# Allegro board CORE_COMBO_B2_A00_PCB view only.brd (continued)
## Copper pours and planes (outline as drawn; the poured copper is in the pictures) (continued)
N41930622 on TOP (solid shape): 121.73,125.34 121.73,123.99 121.98,123.74 121.98,122.04 121.85,121.91 121.22,121.91 121.09,122.04 121.09,124.45 120.84,124.7 120.84,125.34 120.97,125.46 121.6,125.46
N41930626 on TOP (solid shape): 123.51,124.4 123.51,123.56 123.3,123.36 123.3,122.01 123.25,121.96 122.79,121.96 122.74,122.01 122.74,123.43 123,123.69 123.15,123.69 123.25,123.79 123.25,124.4 123.28,124.42 123.48,124.42
N41930661 on BOTTOM (solid shape): 125.09,125.78 125.09,123.88 125.03,123.81 124.01,123.81 123.95,123.88 123.95,124.79 124.07,125.08 123.95,125.38 123.95,125.78 124.08,125.91 124.97,125.91
N41935085 on TOP (solid shape): 63.69,99.94 63.69,98.42 63.56,98.29 62.55,98.29 62.42,98.42 62.42,100.19 62.55,100.32 63.31,100.32
N41935204 on TOP (solid shape): 59.86,92.57 59.86,92.45 59.83,92.42 59.5,92.42 58.9,92.1 58.63,92.08 58.44,91.89 58.43,91.89 58.33,91.78 57.39,91.78 57.36,91.81 57.36,92.46 57.51,92.6 59.83,92.6
N41935208 on TOP (solid shape): 56.61,93.92 56.61,92.59 56.61,92.53 56.61,91.92 56.58,91.88 56.04,91.88 55.98,91.95 55.98,93.94 56.02,93.98 56.55,93.98
N41935210 on TOP (solid shape): 59.5,92.98 59.83,92.98 59.86,92.95 59.86,92.85 59.83,92.83 58.97,92.83 58.95,92.84 58.59,92.98 57.44,92.98 57.43,92.96 57.36,93.03 57.36,93.79 57.41,93.84 58.19,93.84
N42702326 on BOTTOM (solid shape): 176.44,100.47 176.44,98.26 176.36,98.18 175.91,98.18 175.81,98.28 175.81,99.82 175.68,99.94 175.68,100.92 175.72,100.95 175.96,100.95
N42704390 on TOP (solid shape): 216.47,59.04 216.47,58.28 216.41,58.22 215.8,58.22 215.56,58.46 214.98,58.46 214.98,59.32 216.19,59.32
N42704539 on TOP (solid shape): 191.4,111.06 191.4,109.72 191.37,109.69 190.49,109.69 190.38,109.79 190.38,111.06 190.54,111.21 191.25,111.21
N42707454 on TOP (solid shape): 216.42,51.17 216.42,50.41 216.29,50.28 215.02,50.28 214.89,50.41 214.89,51.17 215.02,51.3 216.29,51.3
N42743777 on TOP (solid shape): 91.5,114.19 91.5,110.73 91.37,110.61 90.1,110.61 89.98,110.73 89.98,113.02 90.74,113.78 90.74,114.19 90.79,114.24 91.45,114.24
N42775282 on TOP (solid shape): 192.59,68.19 192.59,64.66 194.04,63.21 194.8,63.21 194.83,63.18 194.83,63.03 194.8,63.01 193.84,63.01 192.48,63.73 192.09,64.12 191.7,64.12 191.45,64.38 191.45,68.19 191.7,68.44 192.34,68.44
N42775282 on BOTTOM (solid shape): 196.51,65.16 196.65,64.84 196.97,64.7 197.31,64.36 197.6,63.96 198.09,64 199.32,64 199.83,63.49 199.83,62.85 199.71,62.73 197.04,62.73 195.06,64.71 194.58,64.71 194.53,64.75 194.32,64.88 194.08,64.85 192.25,64.85 191.96,65.14 191.96,65.65 192.09,65.77 195.9,65.77
N43141708 on BOTTOM (solid shape): outline of 133 points within 164.76,121.45 176.08,125.67
N43141816 on BOTTOM (solid shape): 176.97,134.62 176.97,134.28 176.81,134.11 167.05,134.11 166.58,133.64 166.58,130.42 163.13,130.42 163.07,130.48 163.07,132.58 163.89,132.58 166.04,134.72 176.87,134.72
N46095567 on TOP (solid shape): 69.2,138.85 68.36,138.85 68.36,140.48 69.2,140.48
N46939475 on TOP (solid shape): 190.86,22.43 191.77,22.43 191.81,22.39 191.81,21.98 191.76,21.93 189.58,21.93 189.54,21.97 189.54,22.47 189.6,22.53 190.76,22.53
N46939475 on BOTTOM (solid shape): 191.79,22.69 191.79,22.02 191.79,22.02 191.7,21.93 189.77,21.93 189.62,22.08 189.62,22.35 190.13,22.86 191.61,22.86
N46939509 on TOP (solid shape): 186.51,23.8 186.51,21.93 186.5,21.92 182.92,21.92 182.76,22.08 182.76,23.02 182.84,23.09 183.1,23.09 183.14,23.05 183.14,22.63 183.28,22.5 183.96,22.5 184.06,22.61 184.06,23.02 184.13,23.09 184.39,23.09 184.44,23.04 184.44,22.57 184.5,22.51 184.75,22.51 185.28,23.04 185.28,23.89 185.34,23.95 186.36,23.95
N46939509 on BOTTOM (solid shape): 184.6,23.57 184.52,23.33 184.6,23.09 184.72,22.99 184.88,22.95 185.18,22.65 185.18,22.04 185.06,21.93 183.79,21.93 183.72,22 183.72,23.82 183.89,23.99 184.6,23.99
N46967671 on TOP (solid shape): 195.01,22.81 195.01,22.56 194.38,21.93 193.75,21.93 193.6,22.08 193.6,22.28 193.92,22.6 193.92,22.78 194.05,22.91 194.9,22.91
N46967671 on BOTTOM (solid shape): 192.49,22.83 192.61,22.59 192.86,22.49 194.02,22.49 194.14,22.37 194.14,22.08 193.99,21.93 192.06,21.93 191.94,22.04 191.94,22.78 191.99,22.83
N46967970 on TOP (solid shape): 191.62,25.33 192.08,24.86 192.08,24.57 192.02,24.51 190.99,24.51 190.38,25.12 190.01,25.12 189.93,25.2 189.93,25.55 190.11,25.73 191.22,25.73

Small or netless copper shapes (teardrops, artwork), in the pictures only: 2082 on TOP, 3124 on BOTTOM, 1 on GND1, 671 on IN1, 1 on VCC, 269 on IN2, 566 on IN3, 1 on GND2, 796 on IN4, 1 on GND3

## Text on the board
BOTTOM: list("[Spacing] BOTTOM" "91.Shape to Route Keepin" "0 MIL [DEFAULT]" "0 MIL" "0.00 MIL" "DRC ERROR CLASS/BOTTOM" "[Shape] Route Keepin/All ((-2977.43 -914.53) (7906.82 5074.84))" "[Bottom Shape] GND ((-2977.43 2424.07) (-2857.3 2460.69))" list(-2860.810000 2460.660000) nil)@@@list("kelly1_pan" "2016/03/17 14:49:46" nil "P143000035-PC" "10i-core_combo_b2.20")@@@list("jennifer_hsu" "2016/03/21 14:50:22" nil "p143000039-pc" "10i-core_combo_b2.20") | list("[Spacing] BOTTOM" "96.Shape to Route Keepout" "0 MIL [DEFAULT]" "0 MIL" "0.00 MIL" "DRC ERROR CLASS/BOTTOM" "[Shape] Route Keepout/Bottom ((-2939.39 4419.59) (-2632.39 4726.59))" "[Bottom Shape] GND ((-2977.43 -914.51) (7906.82 5087.85))" list(-2632.390000 4572.890000) nil)@@@list("kelly1_pan" "2016/03/17 14:49:45" nil "P143000035-PC" "10i-core_combo_b2.20")@@@list("jennifer_hsu" "2016/03/21 14:50:30" nil "p143000039-pc" "10i-core_combo_b2.20") | list("[Spacing] BOTTOM" "95.Shape to Route Keepout" "0 MIL [DEFAULT]" "0 MIL" "0.00 MIL" "DRC ERROR CLASS/BOTTOM" "[Shape] Route Keepout/Bottom ((-2348.84 2383.37) (-2041.84 2690.37))" "[Bottom Shape] GND ((-2977.43 -914.51) (7906.82 5087.85))" list(-2091.230000 2424.070000) nil)@@@list("kelly1_pan" "2016/03/17 14:49:44" nil "P143000035-PC" "10i-core_combo_b2.20")@@@list("jennifer_hsu" "2016/03/21 14:50:28" nil "p143000039-pc" "10i-core_combo_b2.20") | list("[Spacing] BOTTOM" "82.Shape to Route Keepin" "0 MIL [DEFAULT]" "0 MIL" "0.00 MIL" "DRC ERROR CLASS/BOTTOM" "[Shape] Route Keepin/All ((-2977.43 -914.53) (7906.82 5074.84))" "[Bottom Shape] GNDA ((-2355.82 4282.82) (-1364.01 4696.91))" list(-1464.240000 4332.710000) nil)@@@list("kelly1_pan" "2016/03/17 14:49:45" nil "P143000035-PC" "10i-core_combo_b2.20")@@@list("jennifer_hsu" "2016/03/21 14:50:10" nil "p143000039-pc" "10i-core_combo_b2.20") | list("[Spacing] BOTTOM" "87.Shape to Route Keepin" "0 MIL [DEFAULT]" "0 MIL" "0.00 MIL" "DRC ERROR CLASS/BOTTOM" "[Shape] Route Keepin/All ((-2977.43 -914.53) (7906.82 5074.84))" "[Bottom Shape] GND ((-1333.98 4144.95) (291.0 5087.85))" list(-1333.980000 4332.710000) nil)@@@list("kelly1_pan" "2016/03/17 14:49:47" nil "P143000035-PC" "10i-core_combo_b2.20")@@@list("jennifer_hsu" "2016/03/21 14:50:16" nil "p143000039-pc" "10i-core_combo_b2.20") | list("[Spacing] BOTTOM" "88.Shape to Route Keepout" "0 MIL [DEFAULT]" "0 MIL" "0.00 MIL" "DRC ERROR CLASS/BOTTOM" "[Shape] Route Keepout/Bottom ((-629.15 4828.23) (-322.15 5135.23))" "[Bottom Shape] GND ((-1333.98 4144.95) (291.0 5087.85))" list(-545.100000 4844.840000) nil)@@@list("kelly1_pan" "2016/03/17 14:49:48" nil "P143000035-PC" "10i-core_combo_b2.20")@@@list("jennifer_hsu" "2016/03/21 14:50:18" nil "p143000039-pc" "10i-core_combo_b2.20") | list("[Spacing] BOTTOM" "97.Drill Hole to Pin" "5 MIL [DEFAULT]" "1.04 MIL" "3.96 MIL" "DRC ERROR CLASS/BOTTOM" "[ThruPin] Dummy (C40D40N) (-294.55 4947.5)" "[ThruPin] GND (<uTiL>cId4188<uTiL>.16) (-270.74 4868.77)" list(-284.640000 4930.130000) nil)@@@list("kelly1_pan" "2016/03/17 14:49:55" nil "P143000035-PC" "10i-core_combo_b2.20")@@@list("jennifer_hsu" "2016/03/21 14:50:32" nil "p143000039-pc" "10i-core_combo_b2.20") | list("[Spacing] BOTTOM" "93.Shape to Route Keepin" "0 MIL [DEFAULT]" "0 MIL" "0.00 MIL" "DRC ERROR CLASS/BOTTOM" "[Shape] Route Keepin/All ((-2977.43 -914.53) (7906.82 5074.84))" "[Bottom Shape] GND ((348.14 4610.0) (1448.58 5074.86))" list(876.750000 4922.470000) nil)@@@list("kelly1_pan" "2016/03/17 14:49:49" nil "P143000035-PC" "10i-core_combo_b2.20")@@@list("jennifer_hsu" "2016/03/21 14:50:25" nil "p143000039-pc" "10i-core_combo_b2.20") | list("[Spacing] BOTTOM" "84.Drill Hole to Pin" "5 MIL [DEFAULT]" "1.05 MIL" "3.95 MIL" "DRC ERROR CLASS/BOTTOM" "[ThruPin] Dummy (C40D40N) (933.78 4947.5)" "[ThruPin] GND (<uTiL>cId4188<uTiL>.17) (909.96 4868.77)" list(923.870000 4930.130000) nil)@@@list("kelly1_pan" "2016/03/17 14:49:39" nil "P143000035-PC" "10i-core_combo_b2.20")@@@list("jennifer_hsu" "2016/03/21 14:50:13" nil "p143000039-pc" "10i-core_combo_b2.20") | list("[Spacing] BOTTOM" "98.Shape to Route Keepin" "0 MIL [DEFAULT]" "0 MIL" "0.00 MIL" "DRC ERROR CLASS/BOTTOM" "[Shape] Route Keepin/All ((-2977.43 -914.53) (7906.82 5074.84))" "[Bottom Shape] GND ((1932.91 4550.54) (2836.64 5074.86))" list(2681.640000 4654.500000) nil)@@@list("kelly1_pan" "2016/03/17 14:49:50" nil "P143000035-PC" "10i-core_combo_b2.20")@@@list("jennifer_hsu" "2016/03/21 14:50:33" nil "p143000039-pc" "10i-core_combo_b2.20") | list("[Spacing] BOTTOM" "83.Shape to Route Keepin" "0 MIL [DEFAULT]" "0 MIL" "0.00 MIL" "DRC ERROR CLASS/BOTTOM" "[Shape] Route Keepin/All ((-2977.43 -914.53) (7906.82 5074.84))" "[Bottom Shape] GND ((3161.34 4517.5) (3444.78 5074.86))" list(3223.730000 4620.110000) nil)@@@list("kelly1_pan" "2016/03/17 14:49:39" nil "P143000035-PC" "10i-core_combo_b2.20")@@@list("jennifer_hsu" "2016/03/21 14:50:12" nil "p143000039-pc" "10i-core_combo_b2.20") | list("[Spacing] BOTTOM" "92.Shape to Route Keepout" "0 MIL [DEFAULT]" "0 MIL" "0.00 MIL" "DRC ERROR CLASS/BOTTOM" "[Shape] Route Keepout/Bottom ((3926.94 3482.78) (4157.17 3713.01))" "[Bottom Shape] GND ((3898.57 3454.37) (4185.57 3741.37))" list(3971.320000 3722.720000) nil)@@@list("kelly1_pan" "2016/03/17 14:49:54" nil "P143000035-PC" "10i-core_combo_b2.20")@@@list("jennifer_hsu" "2016/03/21 14:50:23" nil "p143000039-pc" "10i-core_combo_b2.20") | list("[Spacing] BOTTOM" "99.Shape to Route Keepin" "0 MIL [DEFAULT]" "0 MIL" "0.00 MIL" "DRC ERROR CLASS/BOTTOM" "[Shape] Route Keepin/All ((-2977.43 -914.53) (7906.82 5074.84))" "[Bottom Shape] BATTERY_GND ((5038.71 2723.29) (5493.24 4090.61))" list(5053.080000 2723.290000) nil)@@@list("kelly1_pan" "2016/03/17 14:49:52" nil "P143000035-PC" "10i-core_combo_b2.20")@@@list("jennifer_hsu" "2016/03/21 14:50:34" nil "p143000039-pc" "10i-core_combo_b2.20") | list("[Spacing] BOTTOM" "101.Shape to Route Keepout" "0 MIL [DEFAULT]" "0 MIL" "0.00 MIL" "DRC ERROR CLASS/BOTTOM" "[Shape] Route Keepout/Bottom ((5146.22 3879.01) (5383.2 4115.99))" "[Bottom Shape] BATTERY_GND ((5038.71 2723.29) (5493.24 4090.61))" list(5199.820000 4090.610000) nil)@@@list("kelly1_pan" "2016/03/17 14:49:53" nil "P143000035-PC" "10i-core_combo_b2.20")@@@list("jennifer_hsu" "2016/03/21 14:50:36" nil "p143000039-pc" "10i-core_combo_b2.20") | list("[Spacing] BOTTOM" "100.Shape to Route Keepout" "0 MIL [DEFAULT]" "0 MIL" "0.00 MIL" "DRC ERROR CLASS/BOTTOM" "[Shape] Route Keepout/Bottom ((5146.22 2697.9) (5383.2 2934.88))" "[Bottom Shape] BATTERY_GND ((5038.71 2723.29) (5493.24 4090.61))" list(5343.120000 2898.440000) nil)@@@list("kelly1_pan" "2016/03/17 14:49:53" nil "P143000035-PC" "10i-core_combo_b2.20")@@@list("jennifer_hsu" "2016/03/21 14:50:35" nil "p143000039-pc" "10i-core_combo_b2.20") | list("[Spacing] BOTTOM" "85.Shape to Route Keepin" "0 MIL [DEFAULT]" "0 MIL" "0.00 MIL" "DRC ERROR CLASS/BOTTOM" "[Shape] Route Keepin/All ((-2977.43 -914.53) (7906.82 5074.84))" "[Bottom Shape] AUIDO_GND ((6400.92 2990.01) (7346.97 3893.75))" list(6400.920000 3859.700000) nil)@@@list("kelly1_pan" "2016/03/17 14:49:37" nil "P143000035-PC" "10i-core_combo_b2.20")@@@list("jennifer_hsu" "2016/03/21 14:50:14" nil "p143000039-pc" "10i-core_combo_b2.20") | list("[Spacing] BOTTOM" "90.Shape to Route Keepin" "0 MIL [DEFAULT]" "0 MIL" "0.00 MIL" "DRC ERROR CLASS/BOTTOM" "[Shape] Route Keepin/All ((-2977.43 -914.53) (7906.82 5074.84))" "[Bottom Shape] SIM_GND ((6400.91 2447.7) (7346.98 3320.07))" list(6422.200000 2954.790000) nil)@@@list("kelly1_pan" "2016/03/17 14:49:51" nil "P143000035-PC" "10i-core_combo_b2.20")@@@list("jennifer_hsu" "2016/03/21 14:50:20" nil "p143000039-pc" "10i-core_combo_b2.20") | list("[Spacing] BOTTOM" "86.Shape to Route Keepout" "0 MIL [DEFAULT]" "0 MIL" "0.00 MIL" "DRC ERROR CLASS/BOTTOM" "[Shape] Route Keepout/Bottom ((6465.52 3643.01) (6702.05 3879.55))" "[Bottom Shape] AUIDO_GND ((6400.92 2990.01) (7346.97 3893.75))" list(6702.050000 3759.780000) nil)@@@list("kelly1_pan" "2016/03/17 14:49:38" nil "P143000035-PC" "10i-core_combo_b2.20")@@@list("jennifer_hsu" "2016/03/21 14:50:15" nil "p143000039-pc" "10i-core_combo_b2.20") | list("[Spacing] BOTTOM" "94.Shape to Route Keepin" "0 MIL [DEFAULT]" "0 MIL" "0.00 MIL" "DRC ERROR CLASS/BOTTOM" "[Shape] Route Keepin/All ((-2977.43 -914.53) (7906.82 5074.84))" "[Bottom Shape] GND ((-2977.43 -914.51) (7906.82 5087.85))" list(7110.370000 -900.160000) nil)@@@list("kelly1_pan" "2016/03/17 14:49:40" nil "P143000035-PC" "10i-core_combo_b2.20")@@@list("jennifer_hsu" "2016/03/21 14:50:27" nil "p143000039-pc" "10i-core_combo_b2.20") | list("[Spacing] BOTTOM" "89.Shape to Route Keepout" "0 MIL [DEFAULT]" "0 MIL" "0.00 MIL" "DRC ERROR CLASS/BOTTOM" "[Shape] Route Keepout/Bottom ((7013.55 2440.26) (7250.08 2676.8))" "[Bottom Shape] SIM_GND ((6400.91 2447.7) (7346.98 3320.07))" list(7250.080000 2557.030000) nil)@@@list("kelly1_pan" "2016/03/17 14:49:51" nil "P143000035-PC" "10i-core_combo_b2.20")@@@list("jennifer_hsu" "2016/03/21 14:50:19" nil "p143000039-pc" "10i-core_combo_b2.20")
Ref Des/Silkscreen Bottom: JSIMUAJ1 | JWLAN1 | H16 | JDCIN1 | JSPK1 | JEDP1 | H14 | H13 | JXDP1 | H15 | JRTC1 | JCRT1 | JFAN1 | PJP5813 | JDIMM2 | JDIMM1 | JPSEN1 | JWWAN1 | H18 | JSER1 | JGFX1 | PJP5502 | H19 | JSPI1 | JBAT1 | JDOCK1 | H17 | JUSB2 | JLAN1 | PJP5601 | PJP5603 | JHS1 | PJP5303 | PJP5304 | JIOR1 | JEPC1 | JSEC1 | PJP5812 | JODD1 | PJP5306 | PJP5811 | JRCAM1 | JBAT_PK1 | JBAT_PK2 | JUAJ1 | JSIM1 | JLED1 | JHDMI1 | HDMIU1 | JUSB1 | PJP5913 | PJP5809 | JSTRG1 | PJP5806 | JGPS1 | PJP5602 | PJP5604 | JCSW2 | JSH1 | PJP802 | BOT | 2nd
TOP: list("[Spacing] TOP" "21.Shape to Route Keepin" "0 MIL [DEFAULT]" "0 MIL" "0.00 MIL" "DRC ERROR CLASS/TOP" "[Shape] Route Keepin/All ((-2977.43 -914.53) (7906.82 5074.84))" "[Top Shape] GND ((-2977.43 2424.07) (-2861.29 2460.69))" list(-2864.800000 2460.660000) nil)@@@list("kelly1_pan" "2016/03/17 14:51:45" nil "P143000035-PC" "10i-core_combo_b2.20")@@@list("jennifer_hsu" "2016/03/21 14:48:58" nil "p143000039-pc" "10i-core_combo_b2.20") | list("[Spacing] TOP" "4.Shape to Route Keepin" "0 MIL [DEFAULT]" "0 MIL" "0.00 MIL" "DRC ERROR CLASS/TOP" "[Shape] Route Keepin/All ((-2977.43 -914.53) (7906.82 5074.84))" "[Top Shape] GND ((-2977.43 3702.53) (-2371.51 4709.9))" list(-2660.500000 3717.110000) nil)@@@list("kelly1_pan" "2016/03/17 14:51:54" nil "P143000035-PC" "10i-core_combo_b2.20")@@@list("jennifer_hsu" "2016/03/21 14:48:36" nil "p143000039-pc" "10i-core_combo_b2.20") | list("[Spacing] TOP" "5.Shape to Route Keepout" "0 MIL [DEFAULT]" "0 MIL" "0.00 MIL" "DRC ERROR CLASS/TOP" "[Shape] Route Keepout/Top ((-2939.39 4419.59) (-2632.39 4726.59))" "[Top Shape] GND ((-2977.43 3702.53) (-2371.51 4709.9))" list(-2632.390000 4572.890000) nil)@@@list("kelly1_pan" "2016/03/17 14:51:55" nil "P143000035-PC" "10i-core_combo_b2.20")@@@list("jennifer_hsu" "2016/03/21 14:48:37" nil "p143000039-pc" "10i-core_combo_b2.20") | list("[Spacing] TOP" "20.Shape to Route Keepin" "0 MIL [DEFAULT]" "0 MIL" "0.00 MIL" "DRC ERROR CLASS/TOP" "[Shape] Route Keepin/All ((-2977.43 -914.53) (7906.82 5074.84))" "[Top Shape] GND ((-2977.43 2931.92) (-1940.0 3385.73))" list(-2593.140000 3050.560000) nil)@@@list("kelly1_pan" "2016/03/17 14:51:51" nil "P143000035-PC" "10i-core_combo_b2.20")@@@list("jennifer_hsu" "2016/03/21 14:48:57" nil "p143000039-pc" "10i-core_combo_b2.20") | list("[Spacing] TOP" "11.Shape to Route Keepout" "0 MIL [DEFAULT]" "0 MIL" "0.00 MIL" "DRC ERROR CLASS/TOP" "[Shape] Route Keepout/Top ((-2348.84 2383.37) (-2041.84 2690.37))" "[Top Shape] GND ((-2734.11 -914.51) (7906.82 5087.85))" list(-2091.230000 2424.070000) nil)@@@list("kelly1_pan" "2016/03/17 14:51:48" nil "P143000035-PC" "10i-core_combo_b2.20")@@@list("jennifer_hsu" "2016/03/21 14:48:45" nil "p143000039-pc" "10i-core_combo_b2.20") | list("[Spacing] TOP" "9.Shape to Route Keepin" "0 MIL [DEFAULT]" "0 MIL" "0.00 MIL" "DRC ERROR CLASS/TOP" "[Shape] Route Keepin/All ((-2977.43 -914.53) (7906.82 5074.84))" "[Top Shape] GNDA ((-2355.82 4282.82) (-1364.01 4696.91))" list(-1464.240000 4332.710000) nil)@@@list("kelly1_pan" "2016/03/17 14:51:59" nil "P143000035-PC" "10i-core_combo_b2.20")@@@list("jennifer_hsu" "2016/03/21 14:48:42" nil "p143000039-pc" "10i-core_combo_b2.20") | list("[Spacing] TOP" "14.Shape to Route Keepin" "0 MIL [DEFAULT]" "0 MIL" "0.00 MIL" "DRC ERROR CLASS/TOP" "[Shape] Route Keepin/All ((-2977.43 -914.53) (7906.82 5074.84))" "[Top Shape] GND ((-1333.99 4136.4) (284.0 5087.83))" list(-1333.990000 4332.710000) nil)@@@list("kelly1_pan" "2016/03/17 14:51:58" nil "P143000035-PC" "10i-core_combo_b2.20")@@@list("jennifer_hsu" "2016/03/21 14:48:49" nil "p143000039-pc" "10i-core_combo_b2.20") | list("[Spacing] TOP" "15.Shape to Route Keepout" "0 MIL [DEFAULT]" "0 MIL" "0.00 MIL" "DRC ERROR CLASS/TOP" "[Shape] Route Keepout/Top ((-629.15 4828.23) (-322.15 5135.23))" "[Top Shape] GND ((-1333.99 4136.4) (284.0 5087.83))" list(-545.150000 4844.860000) nil)@@@list("kelly1_pan" "2016/03/17 14:51:58" nil "P143000035-PC" "10i-core_combo_b2.20")@@@list("jennifer_hsu" "2016/03/21 14:48:50" nil "p143000039-pc" "10i-core_combo_b2.20") | list("[Spacing] TOP" "16.Drill Hole to Pin" "5 MIL [DEFAULT]" "1.04 MIL" "3.96 MIL" "DRC ERROR CLASS/TOP" "[ThruPin] Dummy (C40D40N) (-294.55 4947.5)" "[ThruPin] GND (<uTiL>cId4188<uTiL>.16) (-270.74 4868.77)" list(-284.640000 4930.130000) nil)@@@list("kelly1_pan" "2016/03/17 14:52:00" nil "P143000035-PC" "10i-core_combo_b2.20")@@@list("jennifer_hsu" "2016/03/21 14:48:51" nil "p143000039-pc" "10i-core_combo_b2.20") | list("[Spacing] TOP" "13.Shape to Route Keepin" "0 MIL [DEFAULT]" "0 MIL" "0.00 MIL" "DRC ERROR CLASS/TOP" "[Shape] Route Keepin/All ((-2977.43 -914.53) (7906.82 5074.84))" "[Top Shape] GND ((528.0 4712.0) (1448.58 5074.86))" list(687.360000 4922.470000) nil)@@@list("kelly1_pan" "2016/03/17 14:51:46" nil "P143000035-PC" "10i-core_combo_b2.20")@@@list("jennifer_hsu" "2016/03/21 14:48:47" nil "p143000039-pc" "10i-core_combo_b2.20") | list("[Spacing] TOP" "6.Drill Hole to Pin" "5 MIL [DEFAULT]" "1.05 MIL" "3.95 MIL" "DRC ERROR CLASS/TOP" "[ThruPin] Dummy (C40D40N) (933.78 4947.5)" "[ThruPin] GND (<uTiL>cId4188<uTiL>.17) (909.96 4868.77)" list(923.870000 4930.130000) nil)@@@list("kelly1_pan" "2016/03/17 14:51:49" nil "P143000035-PC" "10i-core_combo_b2.20")@@@list("jennifer_hsu" "2016/03/21 14:48:38" nil "p143000039-pc" "10i-core_combo_b2.20") | list("[Spacing] TOP" "12.Shape to Route Keepin" "0 MIL [DEFAULT]" "0 MIL" "0.00 MIL" "DRC ERROR CLASS/TOP" "[Shape] Route Keepin/All ((-2977.43 -914.53) (7906.82 5074.84))" "[Top Shape] GND ((1932.91 4550.54) (2831.6 5074.86))" list(2681.000000 4650.760000) nil)@@@list("kelly1_pan" "2016/03/17 14:51:45" nil "P143000035-PC" "10i-core_combo_b2.20")@@@list("jennifer_hsu" "2016/03/21 14:48:46" nil "p143000039-pc" "10i-core_combo_b2.20") | list("[Spacing] TOP" "3.Shape to Route Keepin" "0 MIL [DEFAULT]" "0 MIL" "0.00 MIL" "DRC ERROR CLASS/TOP" "[Shape] Route Keepin/All ((-2977.43 -914.53) (7906.82 5074.84))" "[Top Shape] GND ((3169.4 4541.5) (3444.78 5074.86))" list(3224.020000 4619.690000) nil)@@@list("kelly1_pan" "2016/03/17 14:51:57" nil "P143000035-PC" "10i-core_combo_b2.20")@@@list("jennifer_hsu" "2016/03/21 14:48:34" nil "p143000039-pc" "10i-core_combo_b2.20") | list("[Spacing] TOP" "19.Shape to Route Keepout" "0 MIL [DEFAULT]" "0 MIL" "0.00 MIL" "DRC ERROR CLASS/TOP" "[Shape] Route Keepout/Top ((5146.22 3879.01) (5383.2 4115.99))" "[Top Shape] BATTERY_GND ((5038.71 2723.29) (5493.24 4090.61))" list(5199.820000 4090.610000) nil)@@@list("kelly1_pan" "2016/03/17 14:51:54" nil "P143000035-PC" "10i-core_combo_b2.20")@@@list("jennifer_hsu" "2016/03/21 14:48:55" nil "p143000039-pc" "10i-core_combo_b2.20") | list("[Spacing] TOP" "18.Shape to Route Keepin" "0 MIL [DEFAULT]" "0 MIL" "0.00 MIL" "DRC ERROR CLASS/TOP" "[Shape] Route Keepin/All ((-2977.43 -914.53) (7906.82 5074.84))" "[Top Shape] BATTERY_GND ((5038.71 2723.29) (5493.24 4090.61))" list(5338.130000 2737.660000) nil)@@@list("kelly1_pan" "2016/03/17 14:51:53" nil "P143000035-PC" "10i-core_combo_b2.20")@@@list("jennifer_hsu" "2016/03/21 14:48:54" nil "p143000039-pc" "10i-core_combo_b2.20") | list("[Spacing] TOP" "17.Shape to Route Keepout" "0 MIL [DEFAULT]" "0 MIL" "0.00 MIL" "DRC ERROR CLASS/TOP" "[Shape] Route Keepout/Top ((5146.22 2697.9) (5383.2 2934.88))" "[Top Shape] BATTERY_GND ((5038.71 2723.29) (5493.24 4090.61))" list(5343.120000 2898.440000) nil)@@@list("kelly1_pan" "2016/03/17 14:51:52" nil "P143000035-PC" "10i-core_combo_b2.20")@@@list("jennifer_hsu" "2016/03/21 14:48:53" nil "p143000039-pc" "10i-core_combo_b2.20") | list("[Spacing] TOP" "2.Shape to Route Keepin" "0 MIL [DEFAULT]" "0 MIL" "0.00 MIL" "DRC ERROR CLASS/TOP" "[Shape] Route Keepin/All ((-2977.43 -914.53) (7906.82 5074.84))" "[Top Shape] SIM_GND ((6400.91 2447.7) (7346.98 3320.07))" list(6422.200000 2954.790000) nil)@@@list("kelly1_pan" "2016/03/17 14:51:56" nil "P143000035-PC" "10i-core_combo_b2.20")@@@list("jennifer_hsu" "2016/03/21 14:48:26" nil "p143000039-pc" "10i-core_combo_b2.20") | list("[Spacing] TOP" "7.Shape to Route Keepout" "0 MIL [DEFAULT]" "0 MIL" "0.00 MIL" "DRC ERROR CLASS/TOP" "[Shape] Route Keepout/Top ((6465.52 3643.01) (6702.05 3879.55))" "[Top Shape] AUIDO_GND ((6400.93 3037.0) (7347.2 3893.76))" list(6702.050000 3759.780000) nil)@@@list("kelly1_pan" "2016/03/17 14:51:50" nil "P143000035-PC" "10i-core_combo_b2.20")@@@list("jennifer_hsu" "2016/03/21 14:48:40" nil "p143000039-pc" "10i-core_combo_b2.20") | list("[Spacing] TOP" "10.Shape to Route Keepin" "0 MIL [DEFAULT]" "0 MIL" "0.00 MIL" "DRC ERROR CLASS/TOP" "[Shape] Route Keepin/All ((-2977.43 -914.53) (7906.82 5074.84))" "[Top Shape] GND ((-2734.11 -914.51) (7906.82 5087.85))" list(7110.370000 -900.160000) nil)@@@list("kelly1_pan" "2016/03/17 14:51:47" nil "P143000035-PC" "10i-core_combo_b2.20")@@@list("jennifer_hsu" "2016/03/21 14:48:44" nil "p143000039-pc" "10i-core_combo_b2.20") | list("[Spacing] TOP" "1.Shape to Route Keepout" "0 MIL [DEFAULT]" "0 MIL" "0.00 MIL" "DRC ERROR CLASS/TOP" "[Shape] Route Keepout/Top ((7013.55 2440.26) (7250.08 2676.8))" "[Top Shape] SIM_GND ((6400.91 2447.7) (7346.98 3320.07))" list(7250.080000 2557.030000) nil)@@@list("kelly1_pan" "2016/03/17 14:51:56" nil "P143000035-PC" "10i-core_combo_b2.20")@@@list("jennifer_hsu" "2016/03/21 14:48:25" nil "p143000039-pc" "10i-core_combo_b2.20") | list("[Spacing] TOP" "8.Shape to Route Keepin" "0 MIL [DEFAULT]" "0 MIL" "0.00 MIL" "DRC ERROR CLASS/TOP" "[Shape] Route Keepin/All ((-2977.43 -914.53) (7906.82 5074.84))" "[Top Shape] AUIDO_GND ((6400.93 3037.0) (7347.2 3893.76))" list(7346.980000 3435.100000) nil)@@@list("kelly1_pan" "2016/03/17 14:51:50" nil "P143000035-PC" "10i-core_combo_b2.20")@@@list("jennifer_hsu" "2016/03/21 14:48:41" nil "p143000039-pc" "10i-core_combo_b2.20")
Ref Des/Silkscreen Top: PJP5902 | PJP5901 | PJP5702 | H10 | H11 | PJP803 | PJP5909 | PJP10 | H5_2 | H3 | H3_2 | PJP5905 | PJP5906 | H22 | H20 | PJP5402 | PJP5403 | PJP5815 | PJP5912 | PJP5401 | JLID1 | JCSW1 | H6 | JTP1 | JDEG2 | JKB1 | H21 | H23 | PJP5501 | JDEG1 | PJP5908 | PJP5810 | JAPS1 | H24 | H12 | H8 | PJP3301 | PJP5301 | PJP5911 | PJP5703 | JFWP1 | H7 | PJP5305 | PJP5201 | PJP805 | PJP5202 | H9 | JTAG1 | H25 | SIM_B2 REV:2.0 (A00) | PCB MADE IN | JSIMUAJ2 | H1 | H2 | PJP6 | H2_2 | PJP5707 | PJP5404 | PJP5903 | PJP5904 | PJP5204 | PJP5203 | PJP5704 | PJP5307 | PJP5308 | BATTERY_B2 REV:2.0 (A00) | H7301 | H7302 | PJP5302 | PJP5701 | PJP5705 | PJP5706 | PJP7 | PJP5708 | TOP | CORE_B2 MAIN BOARD | REV:2.0 (A00) | 2016.03.21 | 2.0/1050mils | 1st | CORE_COMBO_B2 MAIN BOARD REV:2.0 (A00)
GND1: list("[Spacing] GND1" "23.Shape to Route Keepin" "0 MIL [DEFAULT]" "0 MIL" "0.00 MIL" "DRC ERROR CLASS/GND1" "[Shape] Route Keepin/All ((-2977.43 -914.53) (7906.82 5074.84))" "[Gnd1 Shape] GNDA ((-2355.5 3645.0) (-1364.0 4696.91))" list(-1464.240000 4332.710000) nil)@@@list("kelly1_pan" "2016/03/17 14:49:56" nil "P143000035-PC" "10i-core_combo_b2.20")@@@list("jennifer_hsu" "2016/03/21 14:49:00" nil "p143000039-pc" "10i-core_combo_b2.20") | list("[Spacing] GND1" "24.Thru Pin to Thru Pin" "5 MIL [DEFAULT]" "1.04 MIL" "3.96 MIL" "DRC ERROR CLASS/GND1" "[ThruPin] Dummy (C40D40N) (-294.55 4947.5)" "[ThruPin] GND (<uTiL>cId4188<uTiL>.16) (-270.74 4868.77)" list(-284.640000 4930.130000) nil)@@@list("kelly1_pan" "2016/03/17 14:49:58" nil "P143000035-PC" "10i-core_combo_b2.20")@@@list("jennifer_hsu" "2016/03/21 14:49:01" nil "p143000039-pc" "10i-core_combo_b2.20") | list("[Spacing] GND1" "22.Thru Pin to Thru Pin" "5 MIL [DEFAULT]" "1.05 MIL" "3.95 MIL" "DRC ERROR CLASS/GND1" "[ThruPin] Dummy (C40D40N) (933.78 4947.5)" "[ThruPin] GND (<uTiL>cId4188<uTiL>.17) (909.96 4868.77)" list(923.870000 4930.130000) nil)@@@list("kelly1_pan" "2016/03/17 14:49:56" nil "P143000035-PC" "10i-core_combo_b2.20")@@@list("jennifer_hsu" "2016/03/21 14:48:59" nil "p143000039-pc" "10i-core_combo_b2.20") | list("[Spacing] GND1" "25.Shape to Route Keepin" "0 MIL [DEFAULT]" "0 MIL" "0.00 MIL" "DRC ERROR CLASS/GND1" "[Shape] Route Keepin/All ((-2977.43 -914.53) (7906.82 5074.84))" "[Gnd1 Shape] GND ((-2977.43 -914.51) (7906.82 5074.86))" list(7110.370000 -900.160000) nil)@@@list("kelly1_pan" "2016/03/17 14:49:57" nil "P143000035-PC" "10i-core_combo_b2.20")@@@list("jennifer_hsu" "2016/03/21 14:49:03" nil "p143000039-pc" "10i-core_combo_b2.20")
IN1: list("[Spacing] IN1" "27.Shape to Route Keepin" "0 MIL [DEFAULT]" "0 MIL" "0.00 MIL" "DRC ERROR CLASS/IN1" "[Shape] Route Keepin/All ((-2977.43 -914.53) (7906.82 5074.84))" "[In1 Shape] GND ((-2977.43 2424.07) (-2857.3 2460.69))" list(-2860.810000 2460.660000) nil)@@@list("kelly1_pan" "2016/03/17 14:50:09" nil "P143000035-PC" "10i-core_combo_b2.20")@@@list("jennifer_hsu" "2016/03/21 14:49:05" nil "p143000039-pc" "10i-core_combo_b2.20") | list("[Spacing] IN1" "30.Shape to Route Keepin" "0 MIL [DEFAULT]" "0 MIL" "0.00 MIL" "DRC ERROR CLASS/IN1" "[Shape] Route Keepin/All ((-2977.43 -914.53) (7906.82 5074.84))" "[In1 Shape] GNDA ((-2355.82 4282.82) (-1364.01 4696.89))" list(-1464.240000 4332.710000) nil)@@@list("kelly1_pan" "2016/03/17 14:50:09" nil "P143000035-PC" "10i-core_combo_b2.20")@@@list("jennifer_hsu" "2016/03/21 14:49:09" nil "p143000039-pc" "10i-core_combo_b2.20") | list("[Spacing] IN1" "33.Shape to Route Keepin" "0 MIL [DEFAULT]" "0 MIL" "0.00 MIL" "DRC ERROR CLASS/IN1" "[Shape] Route Keepin/All ((-2977.43 -914.53) (7906.82 5074.84))" "[In1 Shape] GND ((-1333.99 4144.0) (1102.88 5074.86))" list(-1333.980000 4332.710000) nil)@@@list("kelly1_pan" "2016/03/17 14:50:11" nil "P143000035-PC" "10i-core_combo_b2.20")@@@list("jennifer_hsu" "2016/03/21 14:49:12" nil "p143000039-pc" "10i-core_combo_b2.20") | list("[Spacing] IN1" "32.Drill Hole to Pin" "5 MIL [DEFAULT]" "1.04 MIL" "3.96 MIL" "DRC ERROR CLASS/IN1" "[ThruPin] Dummy (C40D40N) (-294.55 4947.5)" "[ThruPin] GND (<uTiL>cId4188<uTiL>.16) (-270.74 4868.77)" list(-284.640000 4930.130000) nil)@@@list("kelly1_pan" "2016/03/17 14:50:11" nil "P143000035-PC" "10i-core_combo_b2.20")@@@list("jennifer_hsu" "2016/03/21 14:49:11" nil "p143000039-pc" "10i-core_combo_b2.20") | list("[Spacing] IN1" "26.Drill Hole to Pin" "5 MIL [DEFAULT]" "1.05 MIL" "3.95 MIL" "DRC ERROR CLASS/IN1" "[ThruPin] Dummy (C40D40N) (933.78 4947.5)" "[ThruPin] GND (<uTiL>cId4188<uTiL>.17) (909.96 4868.77)" list(923.870000 4930.130000) nil)@@@list("kelly1_pan" "2016/03/17 14:50:05" nil "P143000035-PC" "10i-core_combo_b2.20")@@@list("jennifer_hsu" "2016/03/21 14:49:04" nil "p143000039-pc" "10i-core_combo_b2.20") | list("[Spacing] IN1" "31.Shape to Route Keepin" "0 MIL [DEFAULT]" "0 MIL" "0.00 MIL" "DRC ERROR CLASS/IN1" "[Shape] Route Keepin/All ((-2977.43 -914.53) (7906.82 5074.84))" "[In1 Shape] GND ((1122.93 4827.42) (1456.73 5012.82))" list(1122.940000 4914.370000) nil)@@@list("kelly1_pan" "2016/03/17 14:50:06" nil "P143000035-PC" "10i-core_combo_b2.20")@@@list("jennifer_hsu" "2016/03/21 14:49:10" nil "p143000039-pc" "10i-core_combo_b2.20") | list("[Spacing] IN1" "29.Shape to Route Keepin" "0 MIL [DEFAULT]" "0 MIL" "0.00 MIL" "DRC ERROR CLASS/IN1" "[Shape] Route Keepin/All ((-2977.43 -914.53) (7906.82 5074.84))" "[In1 Shape] GND ((1923.58 4550.55) (2838.2 5074.86))" list(2680.780000 4648.620000) nil)@@@list("kelly1_pan" "2016/03/17 14:50:06" nil "P143000035-PC" "10i-core_combo_b2.20")@@@list("jennifer_hsu" "2016/03/21 14:49:08" nil "p143000039-pc" "10i-core_combo_b2.20") | list("[Spacing] IN1" "35.Shape to Route Keepin" "0 MIL [DEFAULT]" "0 MIL" "0.00 MIL" "DRC ERROR CLASS/IN1" "[Shape] Route Keepin/All ((-2977.43 -914.53) (7906.82 5074.84))" "[In1 Shape] GND ((3147.86 4550.55) (3444.77 5074.86))" list(3223.730000 4620.110000) nil)@@@list("kelly1_pan" "2016/03/17 14:50:10" nil "P143000035-PC" "10i-core_combo_b2.20")@@@list("jennifer_hsu" "2016/03/21 14:49:14" nil "p143000039-pc" "10i-core_combo_b2.20") | list("[Spacing] IN1" "28.Shape to Route Keepin" "0 MIL [DEFAULT]" "0 MIL" "0.00 MIL" "DRC ERROR CLASS/IN1" "[Shape] Route Keepin/All ((-2977.43 -914.53) (7906.82 5074.84))" "[In1 Shape] BATTERY_GND ((5038.71 2723.29) (5493.24 4090.61))" list(5053.080000 2723.290000) nil)@@@list("kelly1_pan" "2016/03/17 14:50:08" nil "P143000035-PC" "10i-core_combo_b2.20")@@@list("jennifer_hsu" "2016/03/21 14:49:07" nil "p143000039-pc" "10i-core_combo_b2.20") | list("[Spacing] IN1" "34.Shape to Route Keepin" "0 MIL [DEFAULT]" "0 MIL" "0.00 MIL" "DRC ERROR CLASS/IN1" "[Shape] Route Keepin/All ((-2977.43 -914.53) (7906.82 5074.84))" "[In1 Shape] GND ((-2977.43 -914.51) (7906.82 5074.86))" list(7110.370000 -900.160000) nil)@@@list("kelly1_pan" "2016/03/17 14:50:07" nil "P143000035-PC" "10i-core_combo_b2.20")@@@list("jennifer_hsu" "2016/03/21 14:49:13" nil "p143000039-pc" "10i-core_combo_b2.20")
VCC: list("[Spacing] VCC" "39.Shape to Route Keepin" "0 MIL [DEFAULT]" "0 MIL" "0.00 MIL" "DRC ERROR CLASS/VCC" "[Shape] Route Keepin/All ((-2977.43 -914.53) (7906.82 5074.84))" "[Vcc Shape] GNDA ((-2355.5 3645.0) (-1364.0 4696.91))" list(-1464.240000 4332.710000) nil)@@@list("kelly1_pan" "2016/03/17 14:52:02" nil "P143000035-PC" "10i-core_combo_b2.20")@@@list("jennifer_hsu" "2016/03/21 14:49:19" nil "p143000039-pc" "10i-core_combo_b2.20") | list("[Spacing] VCC" "38.Thru Pin to Thru Pin" "5 MIL [DEFAULT]" "1.04 MIL" "3.96 MIL" "DRC ERROR CLASS/VCC" "[ThruPin] Dummy (C40D40N) (-294.55 4947.5)" "[ThruPin] GND (<uTiL>cId4188<uTiL>.16) (-270.74 4868.77)" list(-284.640000 4930.130000) nil)@@@list("kelly1_pan" "2016/03/17 14:52:03" nil "P143000035-PC" "10i-core_combo_b2.20")@@@list("jennifer_hsu" "2016/03/21 14:49:18" nil "p143000039-pc" "10i-core_combo_b2.20") | list("[Spacing] VCC" "36.Thru Pin to Thru Pin" "5 MIL [DEFAULT]" "1.05 MIL" "3.95 MIL" "DRC ERROR CLASS/VCC" "[ThruPin] Dummy (C40D40N) (933.78 4947.5)" "[ThruPin] GND (<uTiL>cId4188<uTiL>.17) (909.96 4868.77)" list(923.870000 4930.130000) nil)@@@list("kelly1_pan" "2016/03/17 14:52:01" nil "P143000035-PC" "10i-core_combo_b2.20")@@@list("jennifer_hsu" "2016/03/21 14:49:15" nil "p143000039-pc" "10i-core_combo_b2.20") | list("[Spacing] VCC" "37.Shape to Route Keepin" "0 MIL [DEFAULT]" "0 MIL" "0.00 MIL" "DRC ERROR CLASS/VCC" "[Shape] Route Keepin/All ((-2977.43 -914.53) (7906.82 5074.84))" "[Vcc Shape] GND ((-2977.43 -914.51) (7906.82 5074.86))" list(7110.370000 -900.160000) nil)@@@list("kelly1_pan" "2016/03/17 14:52:00" nil "P143000035-PC" "10i-core_combo_b2.20")@@@list("jennifer_hsu" "2016/03/21 14:49:16" nil "p143000039-pc" "10i-core_combo_b2.20")
IN2: list("[Spacing] IN2" "44.Shape to Route Keepin" "0 MIL [DEFAULT]" "0 MIL" "0.00 MIL" "DRC ERROR CLASS/IN2" "[Shape] Route Keepin/All ((-2977.43 -914.53) (7906.82 5074.84))" "[In2 Shape] GND ((-2977.43 2424.07) (-2857.3 2460.69))" list(-2860.810000 2460.660000) nil)@@@list("kelly1_pan" "2016/03/17 14:50:16" nil "P143000035-PC" "10i-core_combo_b2.20")@@@list("jennifer_hsu" "2016/03/21 14:49:25" nil "p143000039-pc" "10i-core_combo_b2.20") | list("[Spacing] IN2" "47.Shape to Route Keepin" "0 MIL [DEFAULT]" "0 MIL" "0.00 MIL" "DRC ERROR CLASS/IN2" "[Shape] Route Keepin/All ((-2977.43 -914.53) (7906.82 5074.84))" "[In2 Shape] GNDA ((-2355.82 4282.82) (-1364.01 4696.91))" list(-1464.240000 4332.710000) nil)@@@list("kelly1_pan" "2016/03/17 14:50:13" nil "P143000035-PC" "10i-core_combo_b2.20")@@@list("jennifer_hsu" "2016/03/21 14:49:27" nil "p143000039-pc" "10i-core_combo_b2.20") | list("[Spacing] IN2" "48.Shape to Route Keepin" "0 MIL [DEFAULT]" "0 MIL" "0.00 MIL" "DRC ERROR CLASS/IN2" "[Shape] Route Keepin/All ((-2977.43 -914.53) (7906.82 5074.84))" "[In2 Shape] GND ((-1333.99 4282.84) (1451.02 5074.86))" list(-1333.980000 4332.710000) nil)@@@list("kelly1_pan" "2016/03/17 14:50:17" nil "P143000035-PC" "10i-core_combo_b2.20")@@@list("jennifer_hsu" "2016/03/21 14:49:28" nil "p143000039-pc" "10i-core_combo_b2.20") | list("[Spacing] IN2" "45.Drill Hole to Pin" "5 MIL [DEFAULT]" "1.04 MIL" "3.96 MIL" "DRC ERROR CLASS/IN2" "[ThruPin] Dummy (C40D40N) (-294.55 4947.5)" "[ThruPin] GND (<uTiL>cId4188<uTiL>.16) (-270.74 4868.77)" list(-284.640000 4930.130000) nil)@@@list("kelly1_pan" "2016/03/17 14:50:19" nil "P143000035-PC" "10i-core_combo_b2.20")@@@list("jennifer_hsu" "2016/03/21 14:49:26" nil "p143000039-pc" "10i-core_combo_b2.20") | list("[Spacing] IN2" "40.Drill Hole to Pin" "5 MIL [DEFAULT]" "1.05 MIL" "3.95 MIL" "DRC ERROR CLASS/IN2" "[ThruPin] Dummy (C40D40N) (933.78 4947.5)" "[ThruPin] GND (<uTiL>cId4188<uTiL>.17) (909.96 4868.77)" list(923.870000 4930.130000) nil)@@@list("kelly1_pan" "2016/03/17 14:50:13" nil "P143000035-PC" "10i-core_combo_b2.20")@@@list("jennifer_hsu" "2016/03/21 14:49:20" nil "p143000039-pc" "10i-core_combo_b2.20") | list("[Spacing] IN2" "41.Shape to Route Keepin" "0 MIL [DEFAULT]" "0 MIL" "0.00 MIL" "DRC ERROR CLASS/IN2" "[Shape] Route Keepin/All ((-2977.43 -914.53) (7906.82 5074.84))" "[In2 Shape] GND ((1923.6 4550.55) (2836.71 5074.86))" list(2681.340000 4652.990000) nil)@@@list("kelly1_pan" "2016/03/17 14:50:18" nil "P143000035-PC" "10i-core_combo_b2.20")@@@list("jennifer_hsu" "2016/03/21 14:49:22" nil "p143000039-pc" "10i-core_combo_b2.20") | list("[Spacing] IN2" "42.Shape to Route Keepin" "0 MIL [DEFAULT]" "0 MIL" "0.00 MIL" "DRC ERROR CLASS/IN2" "[Shape] Route Keepin/All ((-2977.43 -914.53) (7906.82 5074.84))" "[In2 Shape] GND ((3147.88 4550.55) (3444.77 5074.86))" list(3223.730000 4620.110000) nil)@@@list("kelly1_pan" "2016/03/17 14:50:17" nil "P143000035-PC" "10i-core_combo_b2.20")@@@list("jennifer_hsu" "2016/03/21 14:49:23" nil "p143000039-pc" "10i-core_combo_b2.20") | list("[Spacing] IN2" "43.Shape to Route Keepin" "0 MIL [DEFAULT]" "0 MIL" "0.00 MIL" "DRC ERROR CLASS/IN2" "[Shape] Route Keepin/All ((-2977.43 -914.53) (7906.82 5074.84))" "[In2 Shape] BATTERY_GND ((5038.71 2723.29) (5493.24 4090.61))" list(5053.080000 2723.290000) nil)@@@list("kelly1_pan" "2016/03/17 14:50:12" nil "P143000035-PC" "10i-core_combo_b2.20")@@@list("jennifer_hsu" "2016/03/21 14:49:24" nil "p143000039-pc" "10i-core_combo_b2.20") | list("[Spacing] IN2" "46.Shape to Route Keepin" "0 MIL [DEFAULT]" "0 MIL" "0.00 MIL" "DRC ERROR CLASS/IN2" "[Shape] Route Keepin/All ((-2977.43 -914.53) (7906.82 5074.84))" "[In2 Shape] GND ((-2977.43 -914.51) (7906.82 5074.86))" list(7110.370000 -900.160000) nil)@@@list("kelly1_pan" "2016/03/17 14:50:14" nil "P143000035-PC" "10i-core_combo_b2.20")@@@list("jennifer_hsu" "2016/03/21 14:49:27" nil "p143000039-pc" "10i-core_combo_b2.20")
IN3: list("[Spacing] IN3" "52.Shape to Route Keepin" "0 MIL [DEFAULT]" "0 MIL" "0.00 MIL" "DRC ERROR CLASS/IN3" "[Shape] Route Keepin/All ((-2977.43 -914.53) (7906.82 5074.84))" "[In3 Shape] GND ((-2977.43 2424.07) (-2857.3 2460.69))" list(-2860.810000 2460.660000) nil)@@@list("kelly1_pan" "2016/03/17 14:51:29" nil "P143000035-PC" "10i-core_combo_b2.20")@@@list("jennifer_hsu" "2016/03/21 14:49:32" nil "p143000039-pc" "10i-core_combo_b2.20") | list("[Spacing] IN3" "60.Shape to Route Keepin" "0 MIL [DEFAULT]" "0 MIL" "0.00 MIL" "DRC ERROR CLASS/IN3" "[Shape] Route Keepin/All ((-2977.43 -914.53) (7906.82 5074.84))" "[In3 Shape] GNDA ((-2355.82 4282.82) (-1364.01 4696.91))" list(-1464.240000 4332.710000) nil)@@@list("kelly1_pan" "2016/03/17 14:51:26" nil "P143000035-PC" "10i-core_combo_b2.20")@@@list("jennifer_hsu" "2016/03/21 14:49:40" nil "p143000039-pc" "10i-core_combo_b2.20") | list("[Spacing] IN3" "49.Shape to Route Keepin" "0 MIL [DEFAULT]" "0 MIL" "0.00 MIL" "DRC ERROR CLASS/IN3" "[Shape] Route Keepin/All ((-2977.43 -914.53) (7906.82 5074.84))" "[In3 Shape] GND ((-1333.99 4282.84) (562.0 5074.86))" list(-1333.990000 4332.710000) nil)@@@list("kelly1_pan" "2016/03/17 14:51:30" nil "P143000035-PC" "10i-core_combo_b2.20")@@@list("jennifer_hsu" "2016/03/21 14:49:29" nil "p143000039-pc" "10i-core_combo_b2.20") | list("[Spacing] IN3" "59.Drill Hole to Pin" "5 MIL [DEFAULT]" "1.04 MIL" "3.96 MIL" "DRC ERROR CLASS/IN3" "[ThruPin] Dummy (C40D40N) (-294.55 4947.5)" "[ThruPin] GND (<uTiL>cId4188<uTiL>.16) (-270.74 4868.77)" list(-284.640000 4930.130000) nil)@@@list("kelly1_pan" "2016/03/17 14:51:34" nil "P143000035-PC" "10i-core_combo_b2.20")@@@list("jennifer_hsu" "2016/03/21 14:49:39" nil "p143000039-pc" "10i-core_combo_b2.20") | list("[Spacing] IN3" "58.Shape to Route Keepin" "0 MIL [DEFAULT]" "0 MIL" "0.00 MIL" "DRC ERROR CLASS/IN3" "[Shape] Route Keepin/All ((-2977.43 -914.53) (7906.82 5074.84))" "[In3 Shape] GND ((514.65 4852.91) (882.65 5020.93))" list(687.360000 4922.470000) nil)@@@list("kelly1_pan" "2016/03/17 14:51:33" nil "P143000035-PC" "10i-core_combo_b2.20")@@@list("jennifer_hsu" "2016/03/21 14:49:38" nil "p143000039-pc" "10i-core_combo_b2.20") | list("[Spacing] IN3" "51.Drill Hole to Pin" "5 MIL [DEFAULT]" "1.05 MIL" "3.95 MIL" "DRC ERROR CLASS/IN3" "[ThruPin] Dummy (C40D40N) (933.78 4947.5)" "[ThruPin] GND (<uTiL>cId4188<uTiL>.17) (909.96 4868.77)" list(923.870000 4930.130000) nil)@@@list("kelly1_pan" "2016/03/17 14:50:21" nil "P143000035-PC" "10i-core_combo_b2.20")@@@list("jennifer_hsu" "2016/03/21 14:49:31" nil "p143000039-pc" "10i-core_combo_b2.20") | list("[Spacing] IN3" "53.Shape to Route Keepin" "0 MIL [DEFAULT]" "0 MIL" "0.00 MIL" "DRC ERROR CLASS/IN3" "[Shape] Route Keepin/All ((-2977.43 -914.53) (7906.82 5074.84))" "[In3 Shape] GND ((941.99 4853.26) (1076.55 5074.86))" list(1027.060000 4944.270000) nil)@@@list("kelly1_pan" "2016/03/17 14:51:27" nil "P143000035-PC" "10i-core_combo_b2.20")@@@list("jennifer_hsu" "2016/03/21 14:49:33" nil "p143000039-pc" "10i-core_combo_b2.20") | list("[Spacing] IN3" "62.Shape to Route Keepin" "0 MIL [DEFAULT]" "0 MIL" "0.00 MIL" "DRC ERROR CLASS/IN3" "[Shape] Route Keepin/All ((-2977.43 -914.53) (7906.82 5074.84))" "[In3 Shape] GND ((1122.93 4844.8) (1456.73 5012.82))" list(1122.940000 4914.370000) nil)@@@list("kelly1_pan" "2016/03/17 14:50:20" nil "P143000035-PC" "10i-core_combo_b2.20")@@@list("jennifer_hsu" "2016/03/21 14:49:43" nil "p143000039-pc" "10i-core_combo_b2.20") | list("[Spacing] IN3" "55.Shape to Route Keepin" "0 MIL [DEFAULT]" "0 MIL" "0.00 MIL" "DRC ERROR CLASS/IN3" "[Shape] Route Keepin/All ((-2977.43 -914.53) (7906.82 5074.84))" "[In3 Shape] GND ((1923.6 4550.55) (2841.28 5074.86))" list(2680.830000 4649.180000) nil)@@@list("kelly1_pan" "2016/03/17 14:51:28" nil "P143000035-PC" "10i-core_combo_b2.20")@@@list("jennifer_hsu" "2016/03/21 14:49:35" nil "p143000039-pc" "10i-core_combo_b2.20") | list("[Spacing] IN3" "57.Shape to Route Keepin" "0 MIL [DEFAULT]" "0 MIL" "0.00 MIL" "DRC ERROR CLASS/IN3" "[Shape] Route Keepin/All ((-2977.43 -914.53) (7906.82 5074.84))" "[In3 Shape] GND ((3147.88 4550.55) (3444.77 5074.86))" list(3223.730000 4620.110000) nil)@@@list("kelly1_pan" "2016/03/17 14:51:27" nil "P143000035-PC" "10i-core_combo_b2.20")@@@list("jennifer_hsu" "2016/03/21 14:49:37" nil "p143000039-pc" "10i-core_combo_b2.20") | list("[Spacing] IN3" "54.Shape to Route Keepin" "0 MIL [DEFAULT]" "0 MIL" "0.00 MIL" "DRC ERROR CLASS/IN3" "[Shape] Route Keepin/All ((-2977.43 -914.53) (7906.82 5074.84))" "[In3 Shape] BATTERY_GND ((5038.71 2723.29) (5493.24 4090.61))" list(5053.080000 2723.290000) nil)@@@list("kelly1_pan" "2016/03/17 14:51:32" nil "P143000035-PC" "10i-core_combo_b2.20")@@@list("jennifer_hsu" "2016/03/21 14:49:34" nil "p143000039-pc" "10i-core_combo_b2.20") | list("[Spacing] IN3" "61.Shape to Route Keepin" "0 MIL [DEFAULT]" "0 MIL" "0.00 MIL" "DRC ERROR CLASS/IN3" "[Shape] Route Keepin/All ((-2977.43 -914.53) (7906.82 5074.84))" "[In3 Shape] AUIDO_GND ((6400.91 2990.01) (7346.98 3893.76))" list(6400.920000 3479.920000) nil)@@@list("kelly1_pan" "2016/03/17 14:51:31" nil "P143000035-PC" "10i-core_combo_b2.20")@@@list("jennifer_hsu" "2016/03/21 14:49:42" nil "p143000039-pc" "10i-core_combo_b2.20") | list("[Spacing] IN3" "56.Shape to Route Keepin" "0 MIL [DEFAULT]" "0 MIL" "0.00 MIL" "DRC ERROR CLASS/IN3" "[Shape] Route Keepin/All ((-2977.43 -914.53) (7906.82 5074.84))" "[In3 Shape] SIM_GND ((6400.91 2447.7) (7346.98 3320.07))" list(6422.200000 2954.790000) nil)@@@list("kelly1_pan" "2016/03/17 14:50:22" nil "P143000035-PC" "10i-core_combo_b2.20")@@@list("jennifer_hsu" "2016/03/21 14:49:36" nil "p143000039-pc" "10i-core_combo_b2.20") | list("[Spacing] IN3" "50.Shape to Route Keepin" "0 MIL [DEFAULT]" "0 MIL" "0.00 MIL" "DRC ERROR CLASS/IN3" "[Shape] Route Keepin/All ((-2977.43 -914.53) (7906.82 5074.84))" "[In3 Shape] GND ((-2977.43 -914.51) (7906.82 5074.86))" list(7110.370000 -900.160000) nil)@@@list("kelly1_pan" "2016/03/17 14:51:34" nil "P143000035-PC" "10i-core_combo_b2.20")@@@list("jennifer_hsu" "2016/03/21 14:49:30" nil "p143000039-pc" "10i-core_combo_b2.20")
GND2: list("[Spacing] GND2" "65.Shape to Route Keepin" "0 MIL [DEFAULT]" "0 MIL" "0.00 MIL" "DRC ERROR CLASS/GND2" "[Shape] Route Keepin/All ((-2977.43 -914.53) (7906.82 5074.84))" "[Gnd2 Shape] GNDA ((-2355.5 3645.0) (-1364.0 4696.91))" list(-1464.240000 4332.710000) nil)@@@list("kelly1_pan" "2016/03/17 14:49:59" nil "P143000035-PC" "10i-core_combo_b2.20")@@@list("jennifer_hsu" "2016/03/21 14:49:49" nil "p143000039-pc" "10i-core_combo_b2.20") | list("[Spacing] GND2" "66.Thru Pin to Thru Pin" "5 MIL [DEFAULT]" "1.04 MIL" "3.96 MIL" "DRC ERROR CLASS/GND2" "[ThruPin] Dummy (C40D40N) (-294.55 4947.5)" "[ThruPin] GND (<uTiL>cId4188<uTiL>.16) (-270.74 4868.77)" list(-284.640000 4930.130000) nil)@@@list("kelly1_pan" "2016/03/17 14:50:01" nil "P143000035-PC" "10i-core_combo_b2.20")@@@list("jennifer_hsu" "2016/03/21 14:49:50" nil "p143000039-pc" "10i-core_combo_b2.20") | list("[Spacing] GND2" "63.Thru Pin to Thru Pin" "5 MIL [DEFAULT]" "1.05 MIL" "3.95 MIL" "DRC ERROR CLASS/GND2" "[ThruPin] Dummy (C40D40N) (933.78 4947.5)" "[ThruPin] GND (<uTiL>cId4188<uTiL>.17) (909.96 4868.77)" list(923.870000 4930.130000) nil)@@@list("kelly1_pan" "2016/03/17 14:50:00" nil "P143000035-PC" "10i-core_combo_b2.20")@@@list("jennifer_hsu" "2016/03/21 14:49:46" nil "p143000039-pc" "10i-core_combo_b2.20") | list("[Spacing] GND2" "64.Shape to Route Keepin" "0 MIL [DEFAULT]" "0 MIL" "0.00 MIL" "DRC ERROR CLASS/GND2" "[Shape] Route Keepin/All ((-2977.43 -914.53) (7906.82 5074.84))" "[Gnd2 Shape] GND ((-2977.43 -914.51) (7906.82 5074.86))" list(7110.370000 -900.160000) nil)@@@list("kelly1_pan" "2016/03/17 14:50:00" nil "P143000035-PC" "10i-core_combo_b2.20")@@@list("jennifer_hsu" "2016/03/21 14:49:47" nil "p143000039-pc" "10i-core_combo_b2.20")
IN4: list("[Spacing] IN4" "73.Shape to Route Keepin" "0 MIL [DEFAULT]" "0 MIL" "0.00 MIL" "DRC ERROR CLASS/IN4" "[Shape] Route Keepin/All ((-2977.43 -914.53) (7906.82 5074.84))" "[In4 Shape] GND ((-2977.43 2424.07) (-2857.3 2460.69))" list(-2860.810000 2460.660000) nil)@@@list("kelly1_pan" "2016/03/17 14:51:36" nil "P143000035-PC" "10i-core_combo_b2.20")@@@list("jennifer_hsu" "2016/03/21 14:49:59" nil "p143000039-pc" "10i-core_combo_b2.20") | list("[Spacing] IN4" "68.Shape to Route Keepin" "0 MIL [DEFAULT]" "0 MIL" "0.00 MIL" "DRC ERROR CLASS/IN4" "[Shape] Route Keepin/All ((-2977.43 -914.53) (7906.82 5074.84))" "[In4 Shape] GNDA ((-2355.82 4282.84) (-1364.01 4696.91))" list(-1464.240000 4332.710000) nil)@@@list("kelly1_pan" "2016/03/17 14:51:42" nil "P143000035-PC" "10i-core_combo_b2.20")@@@list("jennifer_hsu" "2016/03/21 14:49:53" nil "p143000039-pc" "10i-core_combo_b2.20") | list("[Spacing] IN4" "71.Shape to Route Keepin" "0 MIL [DEFAULT]" "0 MIL" "0.00 MIL" "DRC ERROR CLASS/IN4" "[Shape] Route Keepin/All ((-2977.43 -914.53) (7906.82 5074.84))" "[In4 Shape] GND ((-1333.99 4282.84) (325.0 5074.86))" list(-1333.990000 4332.710000) nil)@@@list("kelly1_pan" "2016/03/17 14:51:41" nil "P143000035-PC" "10i-core_combo_b2.20")@@@list("jennifer_hsu" "2016/03/21 14:49:56" nil "p143000039-pc" "10i-core_combo_b2.20") | list("[Spacing] IN4" "74.Drill Hole to Pin" "5 MIL [DEFAULT]" "1.04 MIL" "3.96 MIL" "DRC ERROR CLASS/IN4" "[ThruPin] Dummy (C40D40N) (-294.55 4947.5)" "[ThruPin] GND (<uTiL>cId4188<uTiL>.16) (-270.74 4868.77)" list(-284.640000 4930.130000) nil)@@@list("kelly1_pan" "2016/03/17 14:51:44" nil "P143000035-PC" "10i-core_combo_b2.20")@@@list("jennifer_hsu" "2016/03/21 14:50:00" nil "p143000039-pc" "10i-core_combo_b2.20") | list("[Spacing] IN4" "70.Shape to Route Keepin" "0 MIL [DEFAULT]" "0 MIL" "0.00 MIL" "DRC ERROR CLASS/IN4" "[Shape] Route Keepin/All ((-2977.43 -914.53) (7906.82 5074.84))" "[In4 Shape] GND ((407.21 4587.42) (1396.76 5020.93))" list(687.360000 4922.470000) nil)@@@list("kelly1_pan" "2016/03/17 14:51:37" nil "P143000035-PC" "10i-core_combo_b2.20")@@@list("jennifer_hsu" "2016/03/21 14:49:55" nil "p143000039-pc" "10i-core_combo_b2.20") | list("[Spacing] IN4" "67.Drill Hole to Pin" "5 MIL [DEFAULT]" "1.05 MIL" "3.95 MIL" "DRC ERROR CLASS/IN4" "[ThruPin] Dummy (C40D40N) (933.78 4947.5)" "[ThruPin] GND (<uTiL>cId4188<uTiL>.17) (909.96 4868.77)" list(923.870000 4930.130000) nil)@@@list("kelly1_pan" "2016/03/17 14:51:39" nil "P143000035-PC" "10i-core_combo_b2.20")@@@list("jennifer_hsu" "2016/03/21 14:49:51" nil "p143000039-pc" "10i-core_combo_b2.20") | list("[Spacing] IN4" "75.Shape to Route Keepin" "0 MIL [DEFAULT]" "0 MIL" "0.00 MIL" "DRC ERROR CLASS/IN4" "[Shape] Route Keepin/All ((-2977.43 -914.53) (7906.82 5074.84))" "[In4 Shape] GND ((928.77 4799.88) (1451.02 5074.86))" list(1027.060000 4944.270000) nil)@@@list("kelly1_pan" "2016/03/17 14:51:40" nil "P143000035-PC" "10i-core_combo_b2.20")@@@list("jennifer_hsu" "2016/03/21 14:50:01" nil "p143000039-pc" "10i-core_combo_b2.20") | list("[Spacing] IN4" "76.Shape to Route Keepin" "0 MIL [DEFAULT]" "0 MIL" "0.00 MIL" "DRC ERROR CLASS/IN4" "[Shape] Route Keepin/All ((-2977.43 -914.53) (7906.82 5074.84))" "[In4 Shape] GND ((1923.6 4550.55) (2838.2 5074.86))" list(2680.850000 4649.400000) nil)@@@list("kelly1_pan" "2016/03/17 14:51:37" nil "P143000035-PC" "10i-core_combo_b2.20")@@@list("jennifer_hsu" "2016/03/21 14:50:02" nil "p143000039-pc" "10i-core_combo_b2.20") | list("[Spacing] IN4" "69.Shape to Route Keepin" "0 MIL [DEFAULT]" "0 MIL" "0.00 MIL" "DRC ERROR CLASS/IN4" "[Shape] Route Keepin/All ((-2977.43 -914.53) (7906.82 5074.84))" "[In4 Shape] GND ((3170.0 4550.55) (3444.77 5074.86))" list(3223.730000 4620.110000) nil)@@@list("kelly1_pan" "2016/03/17 14:51:40" nil "P143000035-PC" "10i-core_combo_b2.20")@@@list("jennifer_hsu" "2016/03/21 14:49:54" nil "p143000039-pc" "10i-core_combo_b2.20") | list("[Spacing] IN4" "72.Shape to Route Keepin" "0 MIL [DEFAULT]" "0 MIL" "0.00 MIL" "DRC ERROR CLASS/IN4" "[Shape] Route Keepin/All ((-2977.43 -914.53) (7906.82 5074.84))" "[In4 Shape] BATTERY_GND ((5038.71 2723.29) (5493.24 4090.61))" list(5338.130000 2737.660000) nil)@@@list("kelly1_pan" "2016/03/17 14:51:35" nil "P143000035-PC" "10i-core_combo_b2.20")@@@list("jennifer_hsu" "2016/03/21 14:49:58" nil "p143000039-pc" "10i-core_combo_b2.20") | list("[Spacing] IN4" "77.Shape to Route Keepin" "0 MIL [DEFAULT]" "0 MIL" "0.00 MIL" "DRC ERROR CLASS/IN4" "[Shape] Route Keepin/All ((-2977.43 -914.53) (7906.82 5074.84))" "[In4 Shape] GND ((-2977.43 -914.51) (7906.82 5074.86))" list(7110.370000 -900.160000) nil)@@@list("kelly1_pan" "2016/03/17 14:51:43" nil "P143000035-PC" "10i-core_combo_b2.20")@@@list("jennifer_hsu" "2016/03/21 14:50:04" nil "p143000039-pc" "10i-core_combo_b2.20")
